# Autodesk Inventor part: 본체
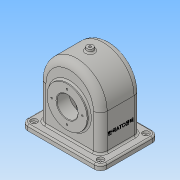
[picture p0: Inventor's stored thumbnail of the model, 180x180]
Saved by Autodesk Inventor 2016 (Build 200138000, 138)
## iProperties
Created: 2018-08
Part Number: 본체
Material: 일반
Document SubType Name: Modeling
Designer: Administrator
Density: 1 g/cm^3
Appearance: 기본값
Mass: 404.475 g
Surface Area: 1182.21 cm^2
Volume: 404.475 cm^3
Author: Administrator
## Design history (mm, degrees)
sketch "스케치1"
  geometry: L1 (58, 0)-(-58, 0); L2 (-58, 0)-(-58, -68); L3 (-58, -68)-(58, -68); L4 (58, -68)-(58, 0); A1 r 58 centre (0, 0) between (58, 0) and (-58, 0); 2 further points
  constraints: 8 end point, 2 coincident, 2 parallel, 2 point on circle, 1 centre point, 1 horizontal, 1 midpoint, 1 perpendicular
  dimensions: "d0" = 116 distance of L3.end L2.end; "d1" = 68 distance of L2.end L1.end
extrude "돌출1" new body sketch "스케치1" stored distance "d2" = 77; taper "d3" = 0 deg
sketch "스케치2"
  geometry: L1 (133, 16.5)-(-17, 16.5); L2 (-17, 16.5)-(-17, -93.5); L3 (-17, -93.5)-(133, -93.5); L4 (133, -93.5)-(133, 16.5); L5 (133, 16.5)-(-17, -93.5); L6 (-17, 16.5)-(133, -93.5); 1 further point
  constraints: 12 end point, 2 midpoint, 2 parallel, 1 horizontal, 1 perpendicular
  dimensions: "d4" = 150 distance of L3.end L2.end; "d5" = 110 distance of L2.end L1.end
extrude "돌출2" join sketch "스케치2" distance "d6" = 10; taper "d7" = 0 deg
feature "쉘2" dims "d11" = 10, "d12" = 6, "d13" = 5
node "작업 평면1"
sketch "스케치3"
  geometry: C1 r 6 at (0, 0); 1 further point
  constraints: 1 centre point, 1 coincident
  dimensions: "d15" = 12 diameter of C1
extrude "돌출3" join sketch "스케치3" stored distance "d16" = 10; taper "d17" = 5 deg
sketch "스케치4"
  geometry: L1 (-96.455, -13)-(96.455, -13); L2 (33.5, -78)-(-33.5, -78) reference; L3 (-33.5, 52)-(-33.5, 0) reference; L4 (-43.5, -13)-(-43.5, 25); L5 (-38.5, 58)-(-38.5, 0) reference; L6 (-43.5, 25)-(-38.5, 25); L7 (-38.5, 25)-(-33.5, 26.747); L8 (-33.5, 26.747)-(-19.5, 15); L9 (-19.5, 15)-(-19.5, -13); L10 (-43.5, -13)-(-19.5, -13); 2 further points
  constraints: 14 end point, 4 point on line, 2 horizontal, 1 collinear, 1 midpoint, 1 perpendicular, 1 vertical, 1 vertical alignment
  dimensions: "d18" = 65 distance between parallel lines of L2 L1; "d19" = 76 diameter of L6 L1; "d20" = 50 deg angle of L9 L8; "d21" = 56 diameter of L8.end L1; "d22" = 5 distance of L4.end L6.end; "d23" = 24 distance between parallel lines of L4 L9
revolve "회전1" sketch "스케치4" stored, may be unused: angle "d24" = 90 deg
sketch "스케치5"
  geometry: L1 (-75, 78)-(75, 78) reference; C1 r 38 at (0, 13); 1 further point
  constraints: 1 centre point, 1 vertical alignment
  dimensions: "d25" = 76 diameter of C1; "d26" = 65 distance from line of L1 C1.centre
extrude "돌출4" join sketch "스케치5" distance "d27" = 10; taper "d28" = 0 deg
hole "구멍1" diameter "d31" = 40; stored, may be unused: countersink angle "d35" = 90 deg, drill point angle "d37" = 118 deg; dims "d29" = 10, "d30" = 10, "d32" = 6, "d33" = 4, "d34" = 2, "d36" = 8
fillet "모깎기1" dims "d38" = 13
fillet "모깎기2" dims "d39" = 3
fillet "모깎기3" dims "d40" = 12
fillet "모깎기4" dims "d41" = 3
chamfer "모따기1" distance "d42" = 1; stored, may be unused: second distance "d43" = 2, angle "d44" = 45 deg
fillet "모깎기5" dims "d45" = 3
fillet "모깎기6" dims "d46" = 3
fillet "모깎기7" dims "d47" = 8
hole "구멍2" diameter "d50" = 4.459; stored, may be unused: countersink angle "d54" = 90 deg, drill point angle "d56" = 118 deg; dims "d48" = 10, "d49" = 10, "d51" = 10, "d52" = 4, "d53" = 2, "d55" = 12.8
node "작업 평면2"
sketch "스케치7"
  geometry: C1 r 21 at (0, -13) reference; 2 further points
  constraints: 1 vertical alignment
  dimensions: "d59" = 29 distance of C1.centre point (0, 16)
hole "구멍3" sketch "스케치7" at (0, 16) diameter "d60" = 3.242; stored, may be unused: countersink angle "d64" = 90 deg, drill point angle "d66" = 118 deg; dims "d61" = 8, "d62" = 4, "d63" = 2, "d65" = 10
node "작업 평면3"
sketch "스케치9"
  geometry: C1 r 21 at (0, -13) reference; 2 further points
  constraints: 1 vertical alignment
  dimensions: "d71" = 29 distance of C1.centre point (0, 16)
hole "구멍4" sketch "스케치9" at (0, 16) diameter "d72" = 3.242; stored, may be unused: countersink angle "d76" = 90 deg, drill point angle "d78" = 118 deg; dims "d73" = 8, "d74" = 4, "d75" = 2, "d77" = 10
hole "구멍5" diameter "d84" = 5; stored, may be unused: countersink angle "d88" = 90 deg, drill point angle "d90" = 0 deg; dims "d82" = 10, "d83" = 10, "d85" = 8, "d86" = 12, "d87" = 4, "d89" = 10
hole "구멍6" diameter "d93" = 5; stored, may be unused: countersink angle "d97" = 90 deg, drill point angle "d99" = 0 deg; dims "d91" = 10, "d92" = 10, "d94" = 8, "d95" = 12, "d96" = 4, "d98" = 10
hole "구멍7" diameter "d102" = 5; stored, may be unused: countersink angle "d106" = 90 deg, drill point angle "d108" = 0 deg; dims "d100" = 10, "d101" = 10, "d103" = 8, "d104" = 12, "d105" = 4, "d107" = 10
hole "구멍8" diameter "d111" = 5; stored, may be unused: countersink angle "d115" = 90 deg, drill point angle "d117" = 0 deg; dims "d109" = 10, "d110" = 10, "d112" = 8, "d113" = 12, "d114" = 4, "d116" = 10
fillet "모깎기8" dims "d118" = 3
sketch "스케치10"
  geometry: L1 (78, 0)-(78, 51) reference; L2 (0, -13)-(65, -13) reference; 2 further points
  constraints: 1 other
  dimensions: "d119" = 40 distance from line of L1 point (38, 25.5); "d120" = 38.5 distance from line of point (38, 25.5) L2
feature "엠보싱1" sketch "스케치10" dims "d12" = 6, "d121" = 0.5, "d122" = 0
sketch "스케치11"
  geometry: L1 (-91.251, 79.717)-(79.571, 79.717); L2 (79.571, 79.717)-(79.571, -102.201); L3 (79.571, -102.201)-(-91.251, -102.201); L4 (-91.251, -102.201)-(-91.251, 79.717); 1 further point
  constraints: 8 end point, 2 parallel, 1 horizontal, 1 perpendicular
extrude "돌출5" cut sketch "스케치11" stored distance "d123" = 10; taper "d124" = 0 deg
node "솔리드1"
pattern_circular "원형 패턴1" dims angle "d68" = 360 deg
pattern_circular "원형 패턴2" dims angle "d80" = 360 deg
other parameters: "d14" = 64, "d58" = -43.5, "d70" = 48.5
